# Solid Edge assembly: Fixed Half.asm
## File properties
Author: Dan
Template: metric assembly.asm
Last saved by: Dan
Revision: 101
Application: Solid Edge
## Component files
Spring Stripper.par
SB M10-20.par
SB M10-100.par
fixed Half Stripper.asm
FH Die Plate.par
Runner Plate.par
LB FBN34-36.par
FH insert Outer.par
FH Insert Inner.par
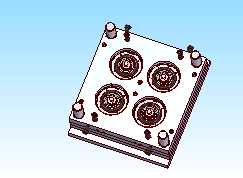
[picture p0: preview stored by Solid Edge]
